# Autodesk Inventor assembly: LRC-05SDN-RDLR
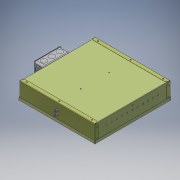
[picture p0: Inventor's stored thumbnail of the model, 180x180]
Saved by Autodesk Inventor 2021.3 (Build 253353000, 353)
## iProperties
load_classification: Lighting
motor: 0 ul
Part Number: LRC-05SDN-RDLR
Document SubType Name: Assembly
Designer: JChurch
description: 0:0:Super Shallow 5-6" Downlight - COB LED
manufacturer: 0:0:The Kirlin Company
model: 0:0:LRC-05SDN
url: 0:0:
Author: JChurch
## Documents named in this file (6)
- X:\Revit Files\0000-Un-Zipped\COB\LRC-05SDN-RDL\LRC-05SDN-RDLR.iam
- X:\INVENTOR\830\830399-00-00.ipt
- X:\INVENTOR\885\885000-00-00.iam
- X:\INVENTOR\750\750905-XX-YY.iam
- X:\INVENTOR\KIRLIN_ENG\725\725075-02-00.ipt
- X:\Revit Files\0000-Un-Zipped\COB\LRC-05SDN-RDL\LRC-05SDN-RDLR_Substitute_1.ipt
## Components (5 placed, 5 different names)
1. 830399-00-00:1 — Mate:1, Mate:2, Mate:3, Mate:4, Mate:5, Angle:1, Insert:2
2. 885000-00-00:1 [sub-assembly] — Mate:4, Mate:5, Angle:1
3. 750905-XX-YY:1 [sub-assembly] — Insert:1, Insert:2
4. 725075-02-00:1 — Insert:1
5. LRC-05SDN-RDLR_Substitute_1:1
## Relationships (8: Mate 5, Insert 2, Angle 1)
- Mate:1: 830399-00-00:1
- Mate:2: 830399-00-00:1
- Mate:3: 830399-00-00:1
- Mate:4: 830399-00-00:1 ↔ 885000-00-00:1
- Mate:5: 830399-00-00:1 ↔ 885000-00-00:1
- Angle:1: 830399-00-00:1 ↔ 885000-00-00:1
- Insert:1: 750905-XX-YY:1 ↔ 725075-02-00:1
- Insert:2: 830399-00-00:1 ↔ 750905-XX-YY:1
